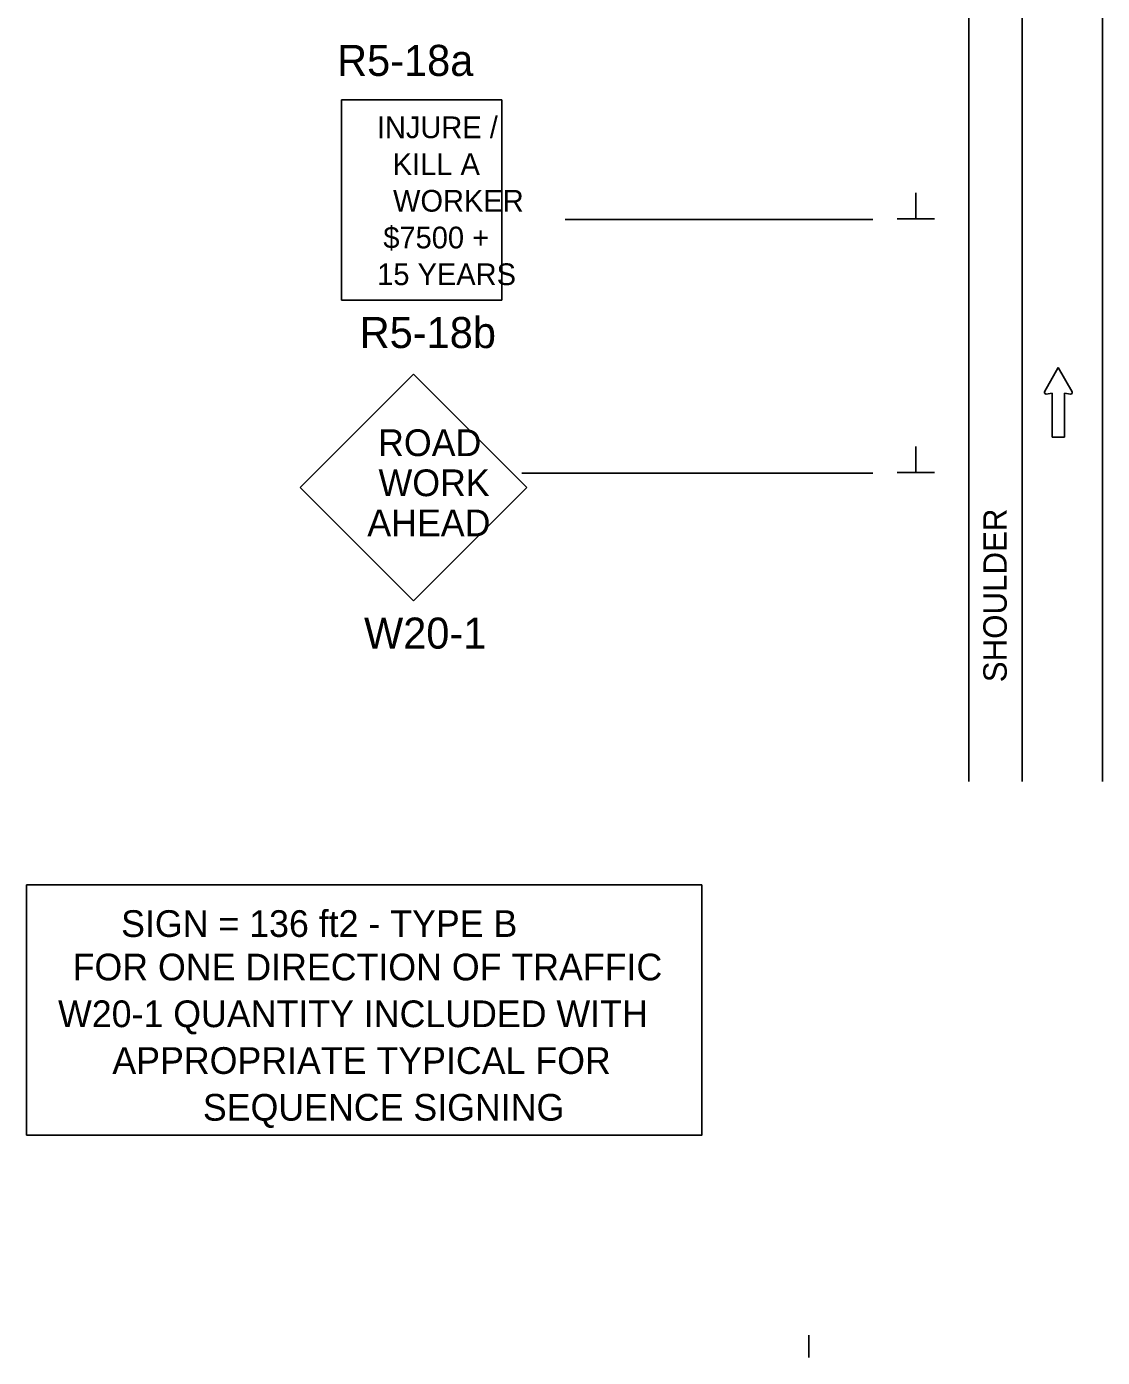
# Model space of a CAD drawing. Extents: x 19017 to 20754, y 4888 to 6104.
# Drawn here: x 19016.9 to 19338.9, y 5088.6 to 5487.1 of the extents above; entities that cross this region are included whole.
import ezdxf

# ---------------------------------------------------------------- set-up
doc = ezdxf.new("R2010")
doc.units = 0
for name, color, linetype in [('BORDER', 7, 'Continuous'), ('MT_SCRATCH_LEVEL_E', 7, 'Continuous'), ('PAVT_EDGE_EX', 7, 'Continuous'), ('TRAFFIC_SIGNS_PR', 7, 'Continuous'), ('TYPICAL_TEXT_DIMEN_PR', 7, 'Continuous')]:
    doc.layers.add(name, color=color, linetype=linetype)

msp = doc.modelspace()

# ---------------------------------------------------------------- linework, layer by layer
at = {"layer": 'BORDER'}
msp.add_line((19251.086, 5088.624), (19251.086, 5095.239), dxfattribs=at)
at = {"layer": 'MT_SCRATCH_LEVEL_E'}
for p, q in [((19325.723, 5384.986), (19321.612, 5377.745)), ((19325.723, 5384.986), (19321.612, 5377.745)), ((19329.87, 5377.745), (19325.723, 5384.986)), ((19329.87, 5377.745), (19325.723, 5384.986)), ((19322.094, 5377.061), (19323.871, 5377.377)), ((19322.094, 5377.061), (19323.871, 5377.377)), ((19323.871, 5377.377), (19323.871, 5364.119)), ((19323.871, 5377.377), (19323.871, 5364.119)), ((19327.613, 5364.119), (19327.613, 5377.377)), ((19327.613, 5377.377), (19329.39, 5377.061)), ((19327.613, 5364.119), (19327.613, 5377.377)), ((19327.613, 5377.377), (19329.39, 5377.061)), ((19323.871, 5364.119), (19327.613, 5364.119)), ((19323.871, 5364.119), (19327.613, 5364.119))]:
    msp.add_line(p, q, dxfattribs=at)
for centre, start, end in [((19322.02, 5377.521), 150.42484, 279.96381), ((19322.02, 5377.521), 150.42484, 279.96381), ((19329.46, 5377.522), 260.03619, 29.77312), ((19329.46, 5377.522), 260.03619, 29.77312)]:
    msp.add_arc(centre, 0.463, start, end, dxfattribs=at)
at = {"layer": 'PAVT_EDGE_EX'}
for p, q in [((19298.917, 6104.026), (19298.917, 5261.047)), ((19314.917, 6104.026), (19314.917, 5261.047)), ((19338.917, 6014.455), (19338.917, 5261.047))]:
    msp.add_line(p, q, dxfattribs=at)
for points in [[(19338.917, 5414.455), (19338.917, 5389.455)], [(19338.917, 5314.455), (19338.917, 5289.455)]]:
    msp.add_lwpolyline(points, dxfattribs=at)
at = {"layer": 'TRAFFIC_SIGNS_PR'}
for p, q in [((19111.123, 5405.134), (19111.123, 5465.134)), ((19159.123, 5465.134), (19111.123, 5465.134)), ((19159.123, 5405.134), (19159.123, 5465.134)), ((19159.123, 5405.134), (19111.123, 5405.134)), ((19132.673, 5383.014), (19098.732, 5349.073)), ((19166.614, 5349.073), (19132.673, 5383.014)), ((19098.732, 5349.073), (19132.673, 5315.132)), ((19132.673, 5315.132), (19166.614, 5349.073))]:
    msp.add_line(p, q, dxfattribs=at)
at = {"layer": 'TYPICAL_TEXT_DIMEN_PR'}
for p, q in [((19283.073, 5429.493), (19283.073, 5437.278)), ((19283.073, 5429.493), (19283.073, 5437.278)), ((19270.246, 5429.331), (19178.112, 5429.331)), ((19270.246, 5429.331), (19178.112, 5429.331)), ((19277.448, 5429.493), (19283.073, 5429.493)), ((19277.448, 5429.493), (19283.073, 5429.493)), ((19283.073, 5429.493), (19288.698, 5429.493)), ((19283.073, 5429.493), (19288.698, 5429.493)), ((19283.073, 5353.576), (19283.073, 5361.361)), ((19270.246, 5353.414), (19165.112, 5353.414)), ((19277.448, 5353.576), (19283.073, 5353.576)), ((19283.073, 5353.576), (19288.698, 5353.576))]:
    msp.add_line(p, q, dxfattribs=at)
msp.add_lwpolyline([(19016.887, 5155.121), (19218.98, 5155.121), (19218.98, 5230.092), (19016.887, 5230.092)], close=True, dxfattribs=at)

# ---------------------------------------------------------------- texts
at = {"layer": 'TRAFFIC_SIGNS_PR'}
for s, height, p in [('R5-18a', 9.3, (19109.83, 5472.316)), ('INJURE /', 6.5, (19121.729, 5453.681)), ('KILL A', 6.5, (19126.479, 5442.681)), ('WORKER', 6.5, (19126.574, 5431.681)), ('$7500 +', 6.5, (19123.666, 5420.682)), ('15 YEARS', 6.5, (19121.829, 5409.682)), ('R5-18b', 9.3, (19116.593, 5390.834)), ('ROAD', 8, (19122.1, 5358.492)), ('WORK', 8, (19122.236, 5346.492)), ('AHEAD', 8, (19118.874, 5334.492)), ('W20-1', 9.3, (19117.885, 5300.833))]:
    msp.add_text(s, height=height, dxfattribs=at).set_placement(p)
at = {"layer": 'TYPICAL_TEXT_DIMEN_PR'}
msp.add_text('SHOULDER', height=7, rotation=90, dxfattribs=at).set_placement((19310.279, 5290.774))
for s, p in [('SIGN = 136 ft2 - TYPE B', (19045.171, 5214.514)), ('FOR ONE DIRECTION OF TRAFFIC', (19030.658, 5201.502)), ('W20-1 QUANTITY INCLUDED WITH ', (19026.3, 5187.502)), ('APPROPRIATE TYPICAL FOR ', (19042.549, 5173.502)), ('SEQUENCE SIGNING', (19069.651, 5159.502))]:
    msp.add_text(s, height=8, dxfattribs=at).set_placement(p)

doc.saveas('drawing.dxf')
